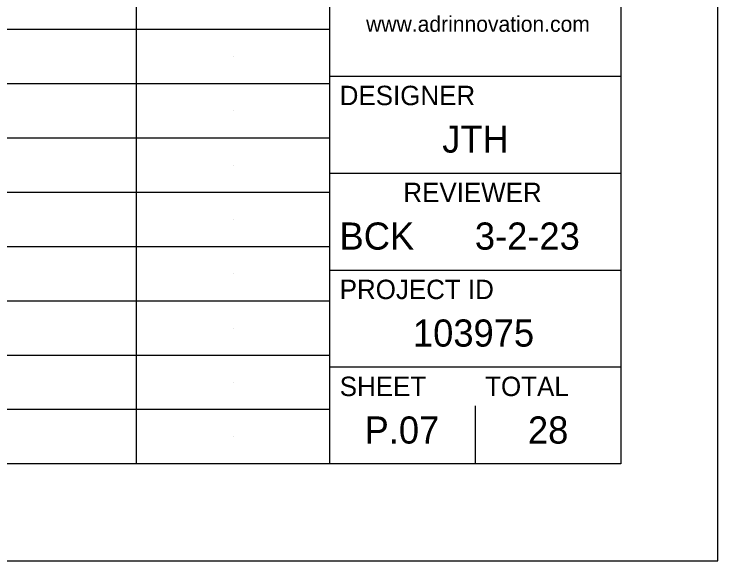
# Model space of a CAD drawing. Extents: x 0 to 34, y 0 to 22.
# Drawn here: x 30.371 to 34, y 0 to 2.82 of the extents above; entities that cross this region are included whole.
import ezdxf

# ---------------------------------------------------------------- set-up
doc = ezdxf.new("R2010")
doc.units = 0
for name, color, linetype in [('SC_Scratch1', 7, 'Continuous'), ('SH_Border', 7, 'Continuous'), ('SH_Cut_Line', 7, 'Continuous'), ('SH_Data', 7, 'Continuous')]:
    doc.layers.add(name, color=color, linetype=linetype)

msp = doc.modelspace()

# ---------------------------------------------------------------- linework, layer by layer
at = {"layer": 'SC_Scratch1'}
for p, q in [((31.5, 2.6), (31.5, 2.6)), ((31.5, 2.32), (31.5, 2.32)), ((31.5, 2.04), (31.5, 2.04)), ((31.5, 1.76), (31.5, 1.76)), ((31.5, 1.48), (31.5, 1.48)), ((31.5, 1.2), (31.5, 1.2)), ((31.5, 0.92), (31.5, 0.92)), ((31.5, 0.64), (31.5, 0.64))]:
    msp.add_line(p, q, dxfattribs=at)
at = {"layer": 'SH_Border'}
for p, q in [((32, 0.5), (32, 21.5)), ((32, 2.5), (33.5, 2.5)), ((32, 2), (33.5, 2)), ((32, 1.5), (33.5, 1.5)), ((32, 1), (33.5, 1))]:
    msp.add_line(p, q, dxfattribs=at)
msp.add_lwpolyline([(1.5, 21.5), (33.5, 21.5), (33.5, 0.5), (1.5, 0.5)], close=True, dxfattribs=at)
at = {"layer": 'SH_Cut_Line'}
msp.add_lwpolyline([(0, 0), (34, 0), (34, 22), (0, 22)], close=True, dxfattribs=at)
at = {"layer": 'SH_Data'}
for p, q in [((31, 21.5), (31, 0.5)), ((32, 2.74), (1.5, 2.74)), ((32, 2.46), (1.5, 2.46)), ((32, 2.18), (1.5, 2.18)), ((32, 1.9), (1.5, 1.9)), ((32, 1.62), (1.5, 1.62)), ((32, 1.34), (1.5, 1.34)), ((32, 1.06), (1.5, 1.06)), ((32.75, 0.5), (32.75, 0.8)), ((32, 0.78), (1.5, 0.78)), ((32.375, 0.675), (32.375, 0.675))]:
    msp.add_line(p, q, dxfattribs=at)

# ---------------------------------------------------------------- texts
for s, height, p in [('www.adrinnovation.com', 0.08125, (32.1864, 2.7281)), ('DESIGNER', 0.1, (32.05, 2.35)), ('JTH', 0.14, (32.5786, 2.105)), ('REVIEWER', 0.1, (32.3783, 1.85)), ('BCK', 0.14, (32.0491, 1.605)), ('3-2-23', 0.14, (32.7469, 1.605)), ('PROJECT ID', 0.1, (32.05, 1.35)), ('103975', 0.14, (32.4277, 1.105)), ('SHEET', 0.1, (32.05, 0.85)), ('TOTAL', 0.1, (32.8, 0.85)), ('P.07', 0.14, (32.1783, 0.605)), ('28', 0.14, (33.0206, 0.605))]:
    msp.add_text(s, height=height, dxfattribs=at).set_placement(p)

doc.saveas('drawing.dxf')
